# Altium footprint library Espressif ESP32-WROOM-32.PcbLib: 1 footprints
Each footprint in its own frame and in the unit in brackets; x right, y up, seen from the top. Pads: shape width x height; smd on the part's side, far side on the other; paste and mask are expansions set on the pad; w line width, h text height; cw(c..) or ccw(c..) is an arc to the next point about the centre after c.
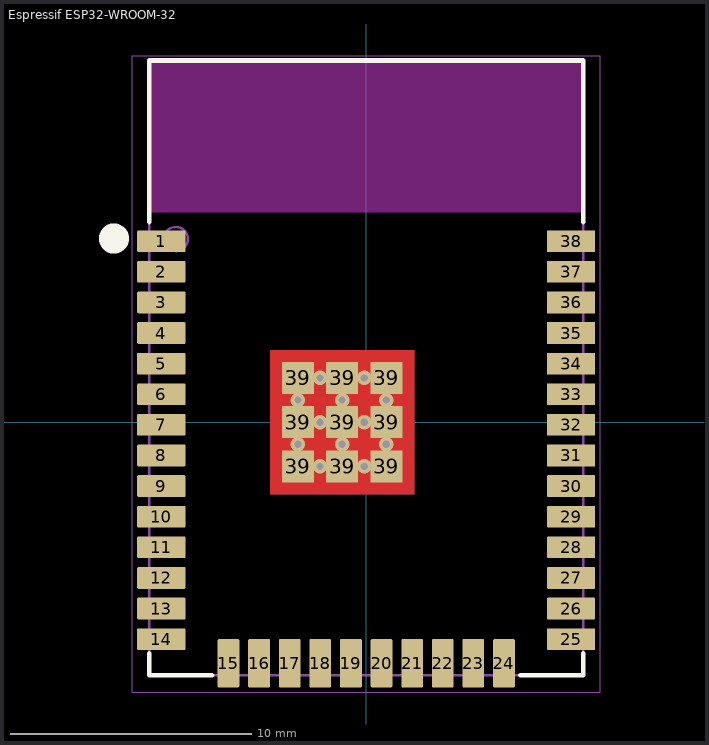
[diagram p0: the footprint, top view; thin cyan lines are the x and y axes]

## Espressif ESP32-WROOM-32 [mm] "39-SMD Module"
height 3.2
pads (47):
  rrect10% 2x0.9 smd paste+0 mask+0.05: 1(-8.5,7.51) 2(-8.5,6.24) 3(-8.5,4.97) 4(-8.5,3.7) 5(-8.5,2.43) 6(-8.5,1.16) 7(-8.5,-0.11) 8(-8.5,-1.38) 9(-8.5,-2.65) 10(-8.5,-3.92) 11(-8.5,-5.19) 12(-8.5,-6.46) 13(-8.5,-7.73) 14(-8.5,-9) 25(8.5,-9) 26(8.5,-7.73) 27(8.5,-6.46) 28(8.5,-5.19) 29(8.5,-3.92) 30(8.5,-2.65)
  rrect10% 0.9x2 smd paste+0 mask+0.05: 15(-5.715,-10) 16(-4.445,-10) 17(-3.175,-10) 18(-1.905,-10) 19(-0.635,-10) 20(0.635,-10) 21(1.905,-10) 22(3.175,-10) 23(4.445,-10) 24(5.715,-10)
  rect 2x0.9 smd paste+0 mask+0.05: 31(8.5,-1.38) 32(8.5,-0.11) 33(8.5,1.16) 34(8.5,2.43) 35(8.5,3.7) 36(8.5,4.97) 37(8.5,6.24) 38(8.5,7.51)
  rect 1.33x1.33 smd paste+0 mask+0.05: 39(-2.835,-1.835) 39(-2.835,0) 39(-2.835,1.835) 39(-1,0) 39(-1,-1.835) 39(-1,1.835) 39(0.835,-1.835) 39(0.835,0) 39(0.835,1.835)
via -1.918,0 diameter 0.6 hole 0.3
via -1.918,1.835 diameter 0.6 hole 0.3
via -0.083,1.835 diameter 0.6 hole 0.3
via -0.083,0 diameter 0.6 hole 0.3
via -1.918,-1.835 diameter 0.6 hole 0.3
via -0.083,-1.835 diameter 0.6 hole 0.3
via -2.835,-0.918 diameter 0.6 hole 0.3
via -2.835,0.917 diameter 0.6 hole 0.3
via -1,-0.918 diameter 0.6 hole 0.3
via -1,0.917 diameter 0.6 hole 0.3
via 0.835,-0.918 diameter 0.6 hole 0.3
via 0.835,0.917 diameter 0.6 hole 0.3
Top Layer:
  rectangle: -4,-3 2,3
Bottom Layer:
  rectangle: -4,-3 2,3
Top Overlay:
  circle w0.75: c-10.465,7.62 r0.25
  lines w0.2: -9,-9.6 -9,-10.5 -6.4,-10.5 ; -9,8.3 -9,15 9,15 9,8.3 ; 6.4,-10.5 9,-10.5 9,-9.6
Keep-Out Layer:
  region: -9,15 9,15 9,8.7 -9,8.7
Mechanical 13:
  circle w0.1: c-7.9,7.6 r0.5
  lines w0.1: -9,-10.5 9,-10.5 9,15 -9,15 -9,-10.5
Mechanical 15:
  lines w0.05: -0.5,0.001 0.5,0.001 ; 0,-0.499 0,0.501 ; -9.7,-11.2 -9.7,15.2 9.7,15.2 9.7,-11.2 -9.7,-11.2
3D body "Espressif - ESP32-WROOM-32.step": height 3.2, standoff 0, extent -9,-10.5 9,15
